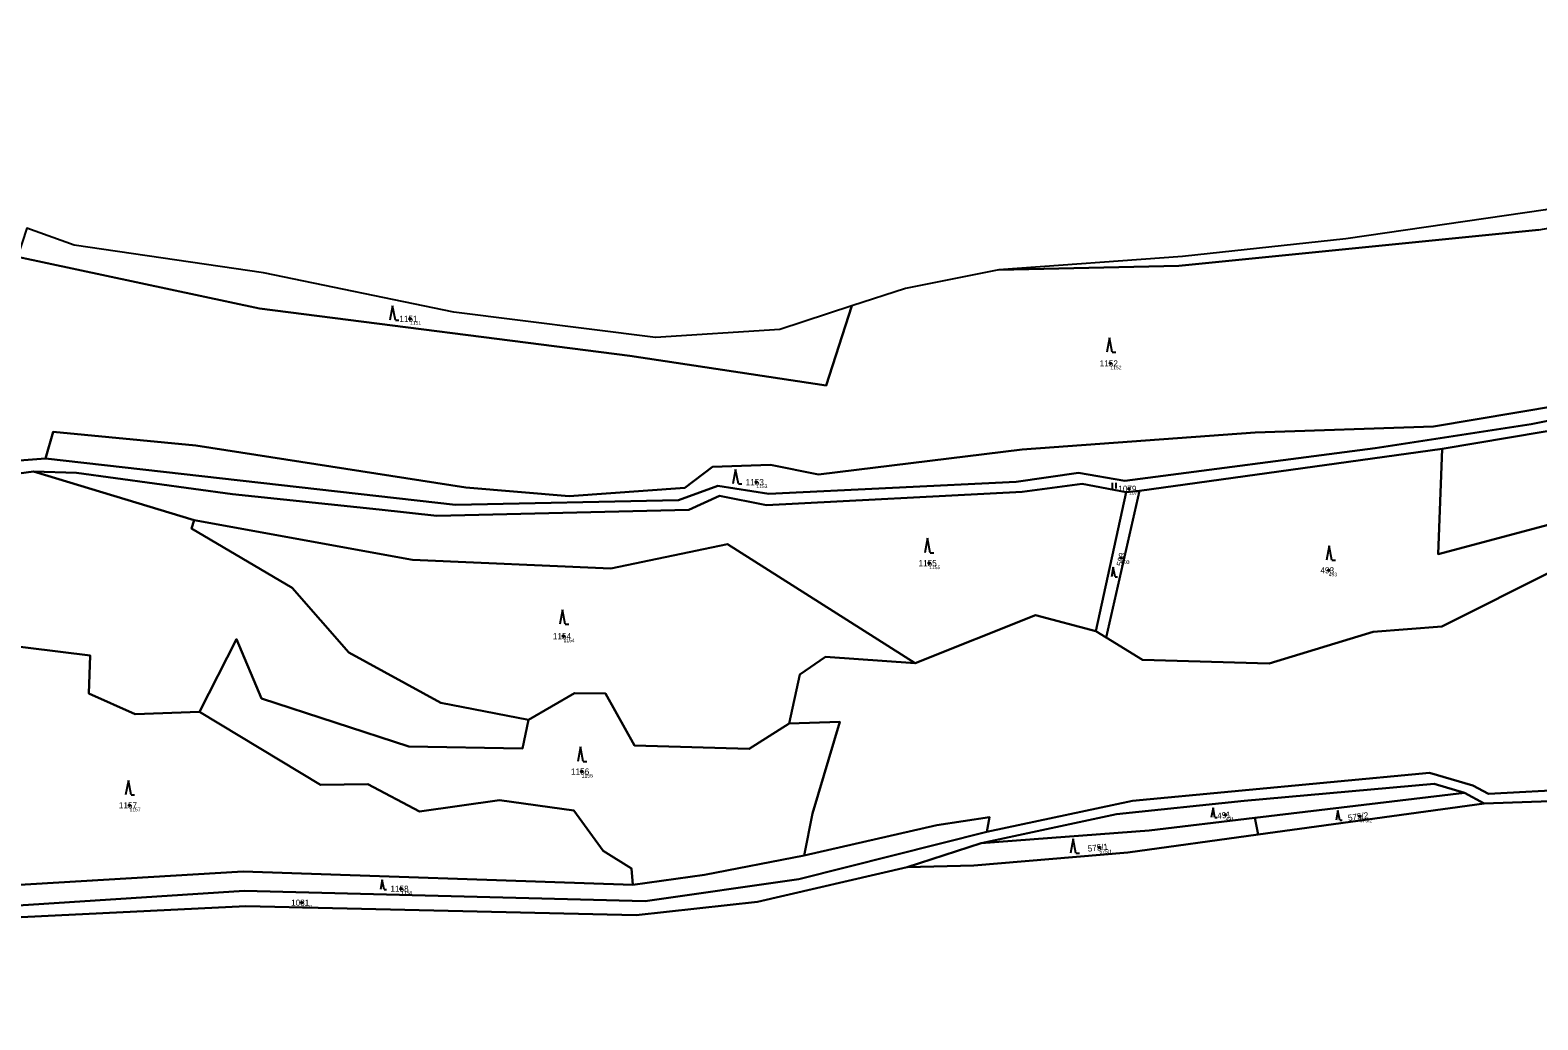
# Model space of a CAD drawing. Extents: x -554500 to -548272, y -1079733 to -1073730.
# Drawn here: x -552756.4 to -552338.3, y -1075642.5 to -1075368 of the extents above; entities that cross this region are included whole.
import ezdxf

# ---------------------------------------------------------------- set-up
doc = ezdxf.new("R2010")
doc.units = 0
for name, color, linetype in [('Definiční body', 7, 'Continuous'), ('Hranice parcel', 7, 'Continuous'), ('Parcelní čísla', 7, 'Continuous'), ('Polygon ku', 7, 'Continuous'), ('Polygon parcely', 7, 'Continuous'), ('Značky kultur', 7, 'Continuous')]:
    doc.layers.add(name, color=color, linetype=linetype)

msp = doc.modelspace()

# ---------------------------------------------------------------- linework, layer by layer
at = {"layer": 'Definiční body'}
for centre in [(-552651.08, -1075448.07994), (-552456.86, -1075460.42994), (-552555.05, -1075493.36994), (-552451.71, -1075495.20994), (-552453.86, -1075514.37994), (-552507.1, -1075515.83994), (-552396.3, -1075517.82994), (-552608.52, -1075536.09994), (-552603.47, -1075573.61994), (-552728.88, -1075582.98994), (-552424.91, -1075585.65994), (-552387.71, -1075586.02994), (-552459.89, -1075594.65994), (-552653.56, -1075606.11994), (-552681.11, -1075609.98994)]:
    msp.add_circle(centre, 0.25, dxfattribs=at)
at = {"layer": 'Hranice parcel'}
for p, q in [((-552487.78, -1075434.54), (-552513.72, -1075439.67)), ((-552513.72, -1075439.67), (-552528.56, -1075444.5)), ((-552528.56, -1075444.5), (-552548.51, -1075451)), ((-552364.85, -1075484.14), (-552448.75, -1075495.78)), ((-552710.97, -1075503.95), (-552755.53, -1075490.42)), ((-552452.53, -1075496.11), (-552460.94, -1075534.66)), ((-552448.75, -1075495.78), (-552458.05, -1075536.43)), ((-552448.75, -1075495.78), (-552452.53, -1075496.11)), ((-552458.05, -1075536.43), (-552460.94, -1075534.66)), ((-552416.8, -1075586.45), (-552358.62, -1075579.52)), ((-552353.24, -1075582.51), (-552358.62, -1075579.52)), ((-552415.86, -1075591.1), (-552353.24, -1075582.51)), ((-552415.86, -1075591.1), (-552416.8, -1075586.45)), ((-552492.72, -1075593.47), (-552513.25, -1075600.1))]:
    msp.add_line(p, q, dxfattribs=at)
for points in [[(-552119.04, -1075370.61), (-552144.01, -1075368.03), (-552170.19, -1075368.64), (-552224.03, -1075379.34), (-552267.92, -1075397.02), (-552301.66, -1075407.04), (-552317.28, -1075413.12), (-552336.21, -1075417.84), (-552391.6, -1075425.89), (-552436.84, -1075430.84), (-552487.78, -1075434.54)], [(-552487.78, -1075434.54), (-552437.86, -1075433.36), (-552338.02, -1075423.37), (-552320.73, -1075420.39), (-552285.63, -1075408.04), (-552263.99, -1075403), (-552241.24, -1075394.42), (-552218.46, -1075384.23), (-552168.52, -1075374.24), (-552141.89, -1075373.39), (-552115.61, -1075378.81), (-552119.15, -1075392.55)], [(-552752.23, -1075486.78), (-552750.02, -1075479.41), (-552710.51, -1075483.17), (-552635.59, -1075494.89), (-552606.97, -1075497.25), (-552574.88, -1075494.93), (-552567.19, -1075489.09), (-552551.1, -1075488.56), (-552537.83, -1075491.28), (-552481.35, -1075484.33), (-552416.76, -1075479.64), (-552367.27, -1075477.93), (-552321.08, -1075470.16), (-552272.63, -1075460.35), (-552228.34, -1075447.55), (-552201.04, -1075436.73), (-552172.82, -1075424.87), (-552135.33, -1075405.75), (-552119.15, -1075392.55)], [(-552117.12, -1075397.55), (-552144.07, -1075415.25), (-552210.55, -1075443.61), (-552251.81, -1075459.73), (-552340.21, -1075477.26), (-552383.4, -1075483.97), (-552452.84, -1075493.02), (-552465.68, -1075490.82), (-552483.01, -1075493.24), (-552551.55, -1075496.61), (-552565.76, -1075494.35), (-552576.61, -1075498.4), (-552638.51, -1075499.68), (-552752.23, -1075486.78)], [(-552548.51, -1075451), (-552583, -1075453.3), (-552638.94, -1075446.19), (-552691.77, -1075435.29), (-552744.22, -1075427.67), (-552757.36, -1075422.97)], [(-552759.97, -1075430.86), (-552692.83, -1075445.19), (-552590.14, -1075458.37), (-552535.69, -1075466.58), (-552528.56, -1075444.5)], [(-552235.87, -1075456.68), (-552250.56, -1075462.65), (-552327.53, -1075477.89), (-552364.85, -1075484.14)], [(-552231.06, -1075477.41), (-552227.57, -1075492.43), (-552251.39, -1075511.69), (-552281.37, -1075527.99), (-552298.01, -1075528.58), (-552333.42, -1075517.58), (-552364.92, -1075533.44), (-552383.95, -1075534.85), (-552412.81, -1075543.63), (-552447.93, -1075542.62), (-552458.05, -1075536.43)], [(-552231.06, -1075477.41), (-552365.93, -1075513.38), (-552364.85, -1075484.14)], [(-552752.23, -1075486.78), (-552769.01, -1075488.08), (-552770.7, -1075488.39)], [(-552755.53, -1075490.42), (-552783.31, -1075494.21), (-552816.95, -1075512.38), (-552854.11, -1075516.41), (-552871.58, -1075515.89), (-552887.55, -1075518.37), (-552914.74, -1075532.56), (-552946.43, -1075542.77), (-552975.28, -1075558.55), (-552983.58, -1075566.46), (-553007.21, -1075580.76), (-553014.23, -1075586.15)], [(-552755.53, -1075490.42), (-552743.59, -1075490.81), (-552700.35, -1075496.66), (-552659.69, -1075500.95), (-552643.69, -1075502.71), (-552573.77, -1075501.05), (-552565.24, -1075497.2), (-552552.27, -1075499.79), (-552481.29, -1075496.1), (-552464.68, -1075493.87), (-552452.53, -1075496.11)], [(-552618.25, -1075559.29), (-552642.51, -1075554.58), (-552668.03, -1075540.6), (-552683.79, -1075522.66), (-552711.69, -1075506.26), (-552710.97, -1075503.95)], [(-552511.03, -1075543.6), (-552563.07, -1075510.61), (-552595.37, -1075517.28), (-552650.45, -1075514.94), (-552710.97, -1075503.95)], [(-552460.94, -1075534.66), (-552477.63, -1075530.26), (-552511.03, -1075543.6)], [(-552820.16, -1075554.69), (-552783.95, -1075536), (-552739.77, -1075541.48), (-552740.13, -1075551.96), (-552727.3, -1075557.68), (-552709.49, -1075557.06)], [(-552709.49, -1075557.06), (-552699.2, -1075536.95), (-552692.31, -1075553.38), (-552651.45, -1075566.65), (-552619.89, -1075567.22), (-552618.25, -1075559.29)], [(-552511.03, -1075543.6), (-552535.83, -1075541.78), (-552542.95, -1075546.7), (-552545.96, -1075560.31)], [(-552618.25, -1075559.29), (-552605.46, -1075551.9), (-552596.84, -1075552), (-552588.8, -1075566.4), (-552557.07, -1075567.3), (-552545.96, -1075560.31)], [(-552709.49, -1075557.06), (-552675.94, -1075577.27), (-552662.82, -1075577.1), (-552648.49, -1075584.66), (-552626.3, -1075581.53), (-552605.7, -1075584.39), (-552597.53, -1075595.59), (-552589.68, -1075600.49), (-552589.31, -1075605.07)], [(-552545.96, -1075560.31), (-552531.94, -1075559.88), (-552539.5, -1075585.22), (-552541.81, -1075596.87)], [(-552491.09, -1075590.37), (-552450.69, -1075581.77), (-552368.41, -1075573.98), (-552356.34, -1075577.53), (-552352.01, -1075579.78), (-552327.88, -1075578.52), (-552277.34, -1075568.48)], [(-552353.24, -1075582.51), (-552329.53, -1075581.64), (-552277.93, -1075572.67)], [(-552358.62, -1075579.52), (-552367.05, -1075577.06), (-552419.76, -1075581.71), (-552455.2, -1075585.4), (-552492.72, -1075593.47)], [(-552541.81, -1075596.87), (-552505, -1075588.49), (-552490.42, -1075586.31), (-552491.09, -1075590.37)], [(-552492.72, -1075593.47), (-552446.07, -1075589.94), (-552416.8, -1075586.45)], [(-552491.09, -1075590.37), (-552543.26, -1075603.44), (-552585.86, -1075609.57), (-552697.1, -1075606.72), (-552794.02, -1075612.99)], [(-552513.25, -1075600.1), (-552494.77, -1075599.65), (-552452.02, -1075596.06), (-552415.86, -1075591.1)], [(-552589.31, -1075605.07), (-552569.41, -1075602.23), (-552541.81, -1075596.87)], [(-552853.01, -1075642.48), (-552844.6, -1075636.93), (-552793.06, -1075615.67), (-552696.65, -1075610.93), (-552588.35, -1075613.46), (-552554.71, -1075609.72), (-552513.25, -1075600.1)], [(-552795.76, -1075610.85), (-552781.16, -1075606.35), (-552697.41, -1075601.32), (-552589.31, -1075605.07)]]:
    msp.add_lwpolyline(points, dxfattribs=at)
at = {"layer": 'Polygon ku'}
msp.add_lwpolyline([(-552336.21, -1075417.84), (-552391.6, -1075425.89), (-552436.84, -1075430.84), (-552487.78, -1075434.54), (-552513.72, -1075439.67), (-552528.56, -1075444.5), (-552548.51, -1075451), (-552583, -1075453.3), (-552638.94, -1075446.19), (-552691.77, -1075435.29), (-552744.22, -1075427.67), (-552757.36, -1075422.97)], dxfattribs=at)
at = {"layer": 'Polygon parcely'}
for points in [[(-552336.21, -1075417.84), (-552391.6, -1075425.89), (-552436.84, -1075430.84), (-552487.78, -1075434.54), (-552437.86, -1075433.36), (-552338.02, -1075423.37)], [(-552338.02, -1075423.37), (-552437.86, -1075433.36), (-552487.78, -1075434.54), (-552513.72, -1075439.67), (-552528.56, -1075444.5), (-552535.69, -1075466.58), (-552590.14, -1075458.37), (-552692.83, -1075445.19), (-552759.97, -1075430.86)], [(-552251.81, -1075459.73), (-552340.21, -1075477.26), (-552383.4, -1075483.97), (-552452.84, -1075493.02), (-552465.68, -1075490.82), (-552483.01, -1075493.24), (-552551.55, -1075496.61), (-552565.76, -1075494.35), (-552576.61, -1075498.4), (-552638.51, -1075499.68), (-552752.23, -1075486.78), (-552769.01, -1075488.08)], [(-552321.08, -1075470.16), (-552367.27, -1075477.93), (-552416.76, -1075479.64), (-552481.35, -1075484.33), (-552537.83, -1075491.28), (-552551.1, -1075488.56), (-552567.19, -1075489.09), (-552574.88, -1075494.93), (-552606.97, -1075497.25), (-552635.59, -1075494.89), (-552710.51, -1075483.17), (-552750.02, -1075479.41), (-552752.23, -1075486.78), (-552638.51, -1075499.68), (-552576.61, -1075498.4), (-552565.76, -1075494.35), (-552551.55, -1075496.61), (-552483.01, -1075493.24), (-552465.68, -1075490.82), (-552452.84, -1075493.02), (-552383.4, -1075483.97), (-552340.21, -1075477.26), (-552251.81, -1075459.73)], [(-552769.01, -1075488.08), (-552752.23, -1075486.78), (-552750.02, -1075479.41), (-552710.51, -1075483.17), (-552635.59, -1075494.89), (-552606.97, -1075497.25), (-552574.88, -1075494.93), (-552567.19, -1075489.09), (-552551.1, -1075488.56), (-552537.83, -1075491.28), (-552481.35, -1075484.33), (-552416.76, -1075479.64), (-552367.27, -1075477.93), (-552321.08, -1075470.16)], [(-552783.31, -1075494.21), (-552755.53, -1075490.42), (-552743.59, -1075490.81), (-552700.35, -1075496.66), (-552659.69, -1075500.95), (-552643.69, -1075502.71), (-552573.77, -1075501.05), (-552565.24, -1075497.2), (-552552.27, -1075499.79), (-552481.29, -1075496.1), (-552464.68, -1075493.87), (-552452.53, -1075496.11), (-552448.75, -1075495.78), (-552364.85, -1075484.14), (-552327.53, -1075477.89)], [(-552783.95, -1075536), (-552739.77, -1075541.48), (-552740.13, -1075551.96), (-552727.3, -1075557.68), (-552709.49, -1075557.06), (-552699.2, -1075536.95), (-552692.31, -1075553.38), (-552651.45, -1075566.65), (-552619.89, -1075567.22), (-552618.25, -1075559.29), (-552642.51, -1075554.58), (-552668.03, -1075540.6), (-552683.79, -1075522.66), (-552711.69, -1075506.26), (-552710.97, -1075503.95), (-552755.53, -1075490.42), (-552783.31, -1075494.21)], [(-552333.42, -1075517.58), (-552364.92, -1075533.44), (-552383.95, -1075534.85), (-552412.81, -1075543.63), (-552447.93, -1075542.62), (-552458.05, -1075536.43), (-552460.94, -1075534.66), (-552477.63, -1075530.26), (-552511.03, -1075543.6), (-552535.83, -1075541.78), (-552542.95, -1075546.7), (-552545.96, -1075560.31), (-552531.94, -1075559.88), (-552539.5, -1075585.22), (-552541.81, -1075596.87), (-552505, -1075588.49), (-552490.42, -1075586.31), (-552491.09, -1075590.37), (-552450.69, -1075581.77), (-552368.41, -1075573.98), (-552356.34, -1075577.53), (-552352.01, -1075579.78), (-552327.88, -1075578.52)], [(-552327.88, -1075578.52), (-552352.01, -1075579.78), (-552356.34, -1075577.53), (-552368.41, -1075573.98), (-552450.69, -1075581.77), (-552491.09, -1075590.37), (-552543.26, -1075603.44), (-552585.86, -1075609.57), (-552697.1, -1075606.72), (-552794.02, -1075612.99)], [(-552793.06, -1075615.67), (-552696.65, -1075610.93), (-552588.35, -1075613.46), (-552554.71, -1075609.72), (-552513.25, -1075600.1), (-552492.72, -1075593.47), (-552455.2, -1075585.4), (-552419.76, -1075581.71), (-552367.05, -1075577.06), (-552358.62, -1075579.52), (-552353.24, -1075582.51), (-552329.53, -1075581.64)], [(-552329.53, -1075581.64), (-552353.24, -1075582.51), (-552415.86, -1075591.1), (-552452.02, -1075596.06), (-552494.77, -1075599.65), (-552513.25, -1075600.1), (-552554.71, -1075609.72), (-552588.35, -1075613.46), (-552696.65, -1075610.93), (-552793.06, -1075615.67)]]:
    msp.add_lwpolyline(points, dxfattribs=at)
for points in [[(-552535.69, -1075466.58), (-552528.56, -1075444.5), (-552548.51, -1075451), (-552583, -1075453.3), (-552638.94, -1075446.19), (-552691.77, -1075435.29), (-552744.22, -1075427.67), (-552757.36, -1075422.97), (-552759.97, -1075430.86), (-552692.83, -1075445.19), (-552590.14, -1075458.37)], [(-552235.87, -1075456.68), (-552250.56, -1075462.65), (-552327.53, -1075477.89), (-552364.85, -1075484.14), (-552365.93, -1075513.38), (-552231.06, -1075477.41)], [(-552458.05, -1075536.43), (-552447.93, -1075542.62), (-552412.81, -1075543.63), (-552383.95, -1075534.85), (-552364.92, -1075533.44), (-552333.42, -1075517.58), (-552298.01, -1075528.58), (-552281.37, -1075527.99), (-552251.39, -1075511.69), (-552227.57, -1075492.43), (-552231.06, -1075477.41), (-552365.93, -1075513.38), (-552364.85, -1075484.14), (-552448.75, -1075495.78)], [(-552511.03, -1075543.6), (-552477.63, -1075530.26), (-552460.94, -1075534.66), (-552452.53, -1075496.11), (-552464.68, -1075493.87), (-552481.29, -1075496.1), (-552552.27, -1075499.79), (-552565.24, -1075497.2), (-552573.77, -1075501.05), (-552643.69, -1075502.71), (-552659.69, -1075500.95), (-552700.35, -1075496.66), (-552743.59, -1075490.81), (-552755.53, -1075490.42), (-552710.97, -1075503.95), (-552650.45, -1075514.94), (-552595.37, -1075517.28), (-552563.07, -1075510.61)], [(-552460.94, -1075534.66), (-552458.05, -1075536.43), (-552448.75, -1075495.78), (-552452.53, -1075496.11)], [(-552595.37, -1075517.28), (-552650.45, -1075514.94), (-552710.97, -1075503.95), (-552711.69, -1075506.26), (-552683.79, -1075522.66), (-552668.03, -1075540.6), (-552642.51, -1075554.58), (-552618.25, -1075559.29), (-552605.46, -1075551.9), (-552596.84, -1075552), (-552588.8, -1075566.4), (-552557.07, -1075567.3), (-552545.96, -1075560.31), (-552542.95, -1075546.7), (-552535.83, -1075541.78), (-552511.03, -1075543.6), (-552563.07, -1075510.61)], [(-552795.76, -1075610.85), (-552781.16, -1075606.35), (-552697.41, -1075601.32), (-552589.31, -1075605.07), (-552589.68, -1075600.49), (-552597.53, -1075595.59), (-552605.7, -1075584.39), (-552626.3, -1075581.53), (-552648.49, -1075584.66), (-552662.82, -1075577.1), (-552675.94, -1075577.27), (-552709.49, -1075557.06), (-552727.3, -1075557.68), (-552740.13, -1075551.96), (-552739.77, -1075541.48), (-552783.95, -1075536), (-552820.16, -1075554.69), (-552841.26, -1075586.93), (-552806.97, -1075597.09)], [(-552648.49, -1075584.66), (-552626.3, -1075581.53), (-552605.7, -1075584.39), (-552597.53, -1075595.59), (-552589.68, -1075600.49), (-552589.31, -1075605.07), (-552569.41, -1075602.23), (-552541.81, -1075596.87), (-552539.5, -1075585.22), (-552531.94, -1075559.88), (-552545.96, -1075560.31), (-552557.07, -1075567.3), (-552588.8, -1075566.4), (-552596.84, -1075552), (-552605.46, -1075551.9), (-552618.25, -1075559.29), (-552619.89, -1075567.22), (-552651.45, -1075566.65), (-552692.31, -1075553.38), (-552699.2, -1075536.95), (-552709.49, -1075557.06), (-552675.94, -1075577.27), (-552662.82, -1075577.1)], [(-552455.2, -1075585.4), (-552492.72, -1075593.47), (-552446.07, -1075589.94), (-552416.8, -1075586.45), (-552358.62, -1075579.52), (-552367.05, -1075577.06), (-552419.76, -1075581.71)], [(-552358.62, -1075579.52), (-552416.8, -1075586.45), (-552415.86, -1075591.1), (-552353.24, -1075582.51)], [(-552491.09, -1075590.37), (-552490.42, -1075586.31), (-552505, -1075588.49), (-552541.81, -1075596.87), (-552569.41, -1075602.23), (-552589.31, -1075605.07), (-552697.41, -1075601.32), (-552781.16, -1075606.35), (-552795.76, -1075610.85), (-552794.02, -1075612.99), (-552697.1, -1075606.72), (-552585.86, -1075609.57), (-552543.26, -1075603.44)], [(-552415.86, -1075591.1), (-552416.8, -1075586.45), (-552446.07, -1075589.94), (-552492.72, -1075593.47), (-552513.25, -1075600.1), (-552494.77, -1075599.65), (-552452.02, -1075596.06)]]:
    msp.add_lwpolyline(points, close=True, dxfattribs=at)
at = {"layer": 'Značky kultur'}
for p, q in [((-552655.92, -1075444.44), (-552656.67, -1075448.44)), ((-552655.17, -1075448.44), (-552655.92, -1075444.44)), ((-552655.17, -1075448.44), (-552654.174, -1075448.44)), ((-552457.08, -1075453.33), (-552457.83, -1075457.33)), ((-552456.33, -1075457.33), (-552457.08, -1075453.33)), ((-552456.33, -1075457.33), (-552455.334, -1075457.33)), ((-552560.79, -1075489.82), (-552561.54, -1075493.82)), ((-552560.04, -1075493.82), (-552560.79, -1075489.82)), ((-552560.04, -1075493.82), (-552559.044, -1075493.82)), ((-552456.301, -1075495.09), (-552456.301, -1075493.59)), ((-552455.3, -1075495.09), (-552455.3, -1075493.59)), ((-552507.58, -1075508.95), (-552508.33, -1075512.95)), ((-552506.83, -1075512.95), (-552507.58, -1075508.95)), ((-552506.83, -1075512.95), (-552505.834, -1075512.95)), ((-552396.22, -1075511.02), (-552396.97, -1075515.02)), ((-552395.47, -1075515.02), (-552396.22, -1075511.02)), ((-552456.07, -1075516.92), (-552456.572, -1075519.6)), ((-552455.568, -1075519.6), (-552456.07, -1075516.92)), ((-552395.47, -1075515.02), (-552394.474, -1075515.02)), ((-552455.568, -1075519.6), (-552454.9, -1075519.6)), ((-552608.83, -1075528.8), (-552609.58, -1075532.8)), ((-552608.08, -1075532.8), (-552608.83, -1075528.8)), ((-552608.08, -1075532.8), (-552607.084, -1075532.8)), ((-552603.8, -1075566.81), (-552604.55, -1075570.81)), ((-552603.05, -1075570.81), (-552603.8, -1075566.81)), ((-552603.05, -1075570.81), (-552602.054, -1075570.81)), ((-552729.21, -1075576.11), (-552729.96, -1075580.11)), ((-552728.46, -1075580.11), (-552729.21, -1075576.11)), ((-552728.46, -1075580.11), (-552727.464, -1075580.11)), ((-552428.4, -1075583.66), (-552428.902, -1075586.34)), ((-552427.898, -1075586.34), (-552428.4, -1075583.66)), ((-552393.77, -1075584.4), (-552394.272, -1075587.08)), ((-552393.268, -1075587.08), (-552393.77, -1075584.4)), ((-552427.898, -1075586.34), (-552427.23, -1075586.34)), ((-552393.268, -1075587.08), (-552392.6, -1075587.08)), ((-552467.17, -1075592.26), (-552467.92, -1075596.26)), ((-552466.42, -1075596.26), (-552467.17, -1075592.26)), ((-552466.42, -1075596.26), (-552465.424, -1075596.26)), ((-552658.81, -1075603.61), (-552659.312, -1075606.29)), ((-552658.308, -1075606.29), (-552658.81, -1075603.61)), ((-552658.308, -1075606.29), (-552657.64, -1075606.29))]:
    msp.add_line(p, q, dxfattribs=at)

# ---------------------------------------------------------------- texts
at = {"layer": 'Definiční body'}
for s, p in [('1151', (-552651.08, -1075449.736)), ('1152', (-552456.86, -1075462.086)), ('1153', (-552555.05, -1075495.026)), ('1079', (-552451.71, -1075496.866)), ('1155', (-552507.1, -1075517.496)), ('503', (-552453.86, -1075516.036)), ('493', (-552396.3, -1075519.486)), ('1154', (-552608.52, -1075537.756)), ('1156', (-552603.47, -1075575.276)), ('1157', (-552728.88, -1075584.646)), ('491', (-552424.91, -1075587.316)), ('575/2', (-552387.71, -1075587.686)), ('575/1', (-552459.89, -1075596.316)), ('1158', (-552653.56, -1075607.776)), ('1081', (-552681.11, -1075611.646))]:
    msp.add_text(s, height=0.999996, dxfattribs=at).set_placement(p)
at = {"layer": 'Parcelní čísla'}
for s, p in [('1151', (-552654.054, -1075448.93)), ('1152', (-552459.834, -1075461.28)), ('1153', (-552558.024, -1075494.22)), ('1079', (-552454.684, -1075496.06)), ('1155', (-552510.074, -1075516.69)), ('493', (-552398.625, -1075518.68)), ('1154', (-552611.494, -1075536.95)), ('1156', (-552606.444, -1075574.47)), ('1157', (-552731.854, -1075583.84)), ('1158', (-552656.534, -1075606.97)), ('1081', (-552684.084, -1075610.84))]:
    msp.add_text(s, height=1.699998, dxfattribs=at).set_placement(p)
for s, rotation, p in [('503', 77, (-552453.554, -1075516.836)), ('491', 7, (-552427.114, -1075586.787)), ('575/2', 8, (-552390.858, -1075587.33)), ('575/1', 6, (-552463.081, -1075595.85))]:
    msp.add_text(s, height=1.699998, rotation=rotation, dxfattribs=at).set_placement(p)

doc.saveas('drawing.dxf')
